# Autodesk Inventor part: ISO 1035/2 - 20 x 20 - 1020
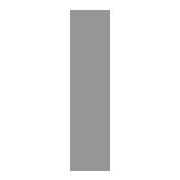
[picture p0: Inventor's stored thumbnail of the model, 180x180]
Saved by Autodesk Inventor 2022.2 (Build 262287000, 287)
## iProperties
_CCFamilyMember: 168
_CCFamilyDisplayName: ISO 1035/2 - 1980 - Barre in acciaio laminate a caldo - Parte 2: barre quadre
_FrameMemberDoc: Frame Member File
_Version: 25.0.0
_GetPNFromCC: 1
Created: 2021-02
Part Number: ISO 1035/2 - 20 x 20 - 1020
Material: Acciaio, Dolce
Description: Barre in acciaio laminate a caldo - Parte 2: barre quadre
Document SubType Name: Modeling
Standard: ISO 1035/2
Designer: 18907419
Standard Revision: First edition 1980-10-15
Standards Organization: ISO
Language: it-IT
Size Designation: 20x 20
Categories: <MemberInstance><Categories><Category DisplayName="Forme strutturali" InternalName="089c4875-fa83-4c05-b084-43b9cc11f5ed" Mnemonic="GRDR"><CategoryParameter Dis
Stock Number: 20x 20
Density: 7.85 g/cm^3
Appearance: Semilucidato
IsCustomPart: 1
G_L: 1020,000 mm
G_W: 20,000 mm
G_H: 20,000 mm
+AEBD2E9C-AE8F-4A22-BA5A-C394ECEA898C+CUTDETAIL1: Angolo retto 45,00 gr
+B7A49465-4835-4679-87DF-84439F735B6F+CUTDETAIL2: Angolo retto 45,00 gr
+DA77D3CE-99E9-4971-B3F3-0C309E4B7C90+CUTDETAIL3: Angolo retto 45,00 gr
+A2FAA2FC-754C-4FE4-BA2F-E865AD32149B+CUTDETAIL4: Angolo retto 45,00 gr
Author: 18907419
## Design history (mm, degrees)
node "Piano iniziale"
node "Piano finale"
sketch "Schizzo"
  geometry: L1 (10, -10)-(-10, -10); L2 (-10, -10)-(-10, 10); L3 (-10, 10)-(10, 10); L4 (10, 10)-(10, -10); L5 (-6, 0)-(8, 0); L6 (0, -30)-(0, 40); L7 (0, 54)-(0, -44) reference; L8 (-14, 0)-(14, 0) reference
  constraints: 12 end point, 2 collinear, 2 parallel, 1 horizontal, 1 perpendicular
  dimensions: "d0" = 20 distance between parallel lines of L3 L1 (= G_W); "d1" = 20 distance between parallel lines of L4 L2 (= G_H); "d4" = 10 distance between parallel lines of L6 L4 (= 0.5 x d1); "d5" = 10 distance between parallel lines of L5 L3 (= 0.5 x d0)
extrude "Corpo" new body sketch "Schizzo" stored distance "d2" = 1020 (= G_L); taper "d3" = 0 deg
node "Driven Length"
  sketch "Sketch3"
    geometry: L1 (0, 0)-(10, 0) reference
    constraints: 2 end point, 1 horizontal
  workplane "Work Plane3"
  sketch "Sketch4"
    geometry: L1 (-2, -10)-(12, -10) reference; L2 (-2, 1010)-(12, 1010) reference
    dimensions: "d9" = 1020 dimension on L1 L2 (derived)
node "Piano di lavoro4"
feature "Divisione1"
node "Piano di lavoro5"
feature "Divisione2"
node "Piano di lavoro6"
feature "Divisione3"
node "Piano di lavoro7"
feature "Divisione4"
body "Solid1"
other parameters: "G_W" = 20 [user parameter; used in 1 equation term], "G_H" = 20 [user parameter; used in 1 equation term], "G_L" = 1020 (= d9) [user parameter; used in 1 equation term], "d8" = 90 deg
